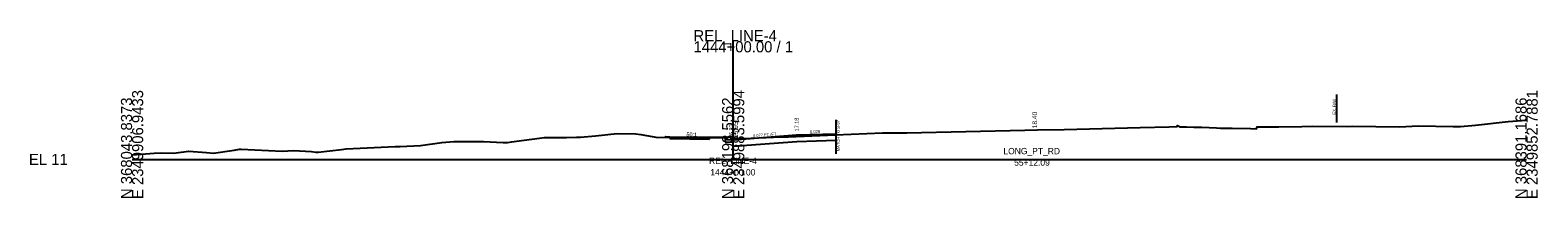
# Model space of a CAD drawing. Extents: x -26 to 2350146, y -10 to 368200.
# Drawn here: x 1974.3 to 2354.4, y 4490.3 to 4532.6 of the extents above; entities that cross this region are included whole.
import ezdxf

# ---------------------------------------------------------------- set-up
doc = ezdxf.new("R2010")
doc.units = 0
for name, color, linetype in [('RD_GPK_XS_Cell', 7, 'Continuous'), ('RD_XS_Base', 7, 'Continuous'), ('RD_XS_CurbBase', 7, 'Continuous'), ('RD_XS_CurbFront', 7, 'Continuous'), ('RD_XS_CurbTop', 7, 'Continuous'), ('RD_XS_EarthShd', 7, 'Continuous'), ('RD_XS_ExGround', 7, 'Continuous'), ('RD_XS_ExRW', 7, 'Continuous'), ('RD_XS_Pave', 7, 'Continuous'), ('RD_XS_SW', 7, 'Continuous'), ('RD_XS_SWbase', 7, 'Continuous'), ('RD_XS_TieSlope', 7, 'Continuous'), ('RD_XS_TX_Elev_EX', 7, 'Continuous'), ('RD_XS_TX_Elev_PR', 7, 'Continuous'), ('RD_XS_TX_MatchLine', 7, 'Continuous'), ('RD_XS_TX_Slope', 7, 'Continuous'), ('RD_XS_TX_Station', 7, 'Continuous'), ('RD_XS_TX_TOC', 7, 'Continuous')]:
    doc.layers.add(name, color=color, linetype=linetype)

msp = doc.modelspace()

# ---------------------------------------------------------------- linework, layer by layer
at = {"layer": 'RD_GPK_XS_Cell'}
for p, q in [((2151.53, 4500), (2151.53, 4529.79)), ((2000, 4500), (2151.53, 4500)), ((2151.53, 4500), (2351.53, 4500))]:
    msp.add_line(p, q, dxfattribs=at)
at = {"layer": 'RD_XS_Base'}
for p, q in [((2151.53, 4503.31), (2167.61, 4504.55)), ((2167.61, 4504.55), (2177.45, 4504.83))]:
    msp.add_line(p, q, dxfattribs=at)
at = {"layer": 'RD_XS_CurbBase'}
for p, q in [((2149.53, 4505.35), (2149.53, 4504.35)), ((2149.53, 4504.35), (2150.03, 4504.35)), ((2150.03, 4504.35), (2151.53, 4504.43)), ((2151.53, 4503.31), (2151.53, 4504.43))]:
    msp.add_line(p, q, dxfattribs=at)
at = {"layer": 'RD_XS_CurbFront'}
msp.add_line((2151.53, 4504.43), (2151.53, 4504.93), dxfattribs=at)
at = {"layer": 'RD_XS_CurbTop'}
for p, q in [((2150.03, 4505.35), (2149.53, 4505.35)), ((2150.11, 4504.85), (2150.03, 4505.35)), ((2151.53, 4504.93), (2150.11, 4504.85)), ((2151.53, 4504.95), (2151.53, 4504.93))]:
    msp.add_line(p, q, dxfattribs=at)
at = {"layer": 'RD_XS_EarthShd'}
for p, q in [((2135.53, 4505.63), (2134.53, 4505.65)), ((2149.53, 4505.35), (2145.53, 4505.43))]:
    msp.add_line(p, q, dxfattribs=at)
at = {"layer": 'RD_XS_ExGround'}
msp.add_lwpolyline([(2000, 4501.13), (2005.54, 4501.58), (2007.53, 4501.62), (2010.44, 4501.58), (2014.34, 4502.08), (2018.8, 4501.72), (2020.51, 4501.59), (2025.7, 4502.37), (2027.08, 4502.55), (2027.5, 4502.56), (2037.82, 4502.04), (2040.66, 4502.24), (2045.21, 4501.96), (2046.31, 4501.84), (2046.9, 4501.83), (2052.77, 4502.5), (2053.96, 4502.65), (2066.36, 4503.28), (2066.98, 4503.27), (2067.62, 4503.28), (2072.71, 4503.48), (2078.06, 4504.27), (2080.1, 4504.4), (2081.1, 4504.51), (2088.61, 4504.53), (2093.58, 4504.29), (2094.32, 4504.28), (2094.65, 4504.27), (2095.66, 4504.44), (2103.93, 4505.5), (2109.49, 4505.5), (2112.01, 4505.62), (2113.01, 4505.6), (2116.8, 4505.93), (2122.26, 4506.57), (2126.97, 4506.42), (2128.23, 4506.25), (2132.5, 4505.5), (2135.98, 4505.64), (2143.57, 4505.59), (2150.21, 4505.69), (2150.76, 4505.69), (2150.93, 4505.19), (2151.53, 4505.22), (2152.54, 4505.28), (2156.03, 4505.39), (2163.59, 4505.67), (2165.43, 4505.73), (2189.2, 4506.66), (2190.27, 4506.66), (2195.33, 4506.71), (2225.08, 4507.36), (2228.21, 4507.42), (2234.96, 4507.58), (2254.16, 4508.05), (2261.43, 4508.22), (2263.41, 4508.27), (2263.54, 4508.51), (2264.17, 4508.25), (2265.82, 4508.21), (2267.69, 4508.16), (2269.64, 4508.09), (2273.4, 4507.93), (2274.33, 4507.88), (2277.3, 4507.84), (2281.92, 4507.76), (2283.45, 4507.68), (2283.62, 4508.18), (2284.13, 4508.18), (2285.77, 4508.19), (2289.11, 4508.19), (2294.86, 4508.32), (2297.55, 4508.4), (2306.37, 4508.31), (2307.53, 4508.34), (2313.53, 4508.26), (2319.57, 4508.18), (2324.24, 4508.48), (2333.03, 4508.32), (2334.87, 4508.31), (2338.64, 4508.66), (2346.89, 4509.59), (2351.53, 4509.93)], dxfattribs=at)
at = {"layer": 'RD_XS_ExRW'}
msp.add_line((2303.69, 4509.34), (2303.69, 4516.34), dxfattribs=at)
at = {"layer": 'RD_XS_Pave'}
for p, q in [((2177.45, 4501.38), (2177.45, 4509.95)), ((2151.53, 4504.95), (2167.53, 4506.18)), ((2167.53, 4506.18), (2177.45, 4506.46))]:
    msp.add_line(p, q, dxfattribs=at)
at = {"layer": 'RD_XS_SW'}
msp.add_line((2145.53, 4505.43), (2135.53, 4505.63), dxfattribs=at)
at = {"layer": 'RD_XS_SWbase'}
for p, q in [((2135.53, 4505.63), (2135.53, 4505.29)), ((2135.53, 4505.29), (2145.53, 4505.09)), ((2145.53, 4505.09), (2145.53, 4505.43))]:
    msp.add_line(p, q, dxfattribs=at)
at = {"layer": 'RD_XS_TieSlope'}
msp.add_line((2134.53, 4505.65), (2134.39, 4505.57), dxfattribs=at)

# ---------------------------------------------------------------- texts
at = {"layer": 'RD_GPK_XS_Cell'}
for s, p in [('REL_LINE-4', (2141.53, 4529.79)), ('1444+00.00 / 1', (2141.53, 4526.99)), ('EL 11', (1974, 4498.6))]:
    msp.add_text(s, height=2.8, dxfattribs=at).set_placement(p)
for s, p in [('N 368043.8373', (2000, 4490)), ('E 2349906.9433', (2002.8, 4490)), ('N 368193.5562', (2151.53, 4490)), ('E 2349883.5994', (2154.33, 4490)), ('N 368391.1686', (2351.53, 4490)), ('E 2349852.7881', (2354.33, 4490))]:
    msp.add_text(s, height=2.8, rotation=90, dxfattribs=at).set_placement(p)
at = {"layer": 'RD_XS_ExRW'}
msp.add_text('EX. R/W ', height=0.75, rotation=90, dxfattribs=at).set_placement((2303.43, 4511.29))
at = {"layer": 'RD_XS_TX_Elev_EX'}
msp.add_text('16.22', height=1, rotation=90, dxfattribs=at).set_placement((2151.5, 4505.39))
at = {"layer": 'RD_XS_TX_Elev_PR'}
for s, height, rotation, p in [(' 18.40', 1.2, 90, (2228.13, 4507.4)), (' 15.95', 1.2, 90, (2152.73, 4504.95)), ('17.18', 1, 90, (2168.03, 4507.07)), ('50:1', 1, 358.8542, (2139.74, 4505.81))]:
    msp.add_text(s, height=height, rotation=rotation, dxfattribs=at).set_placement(p)
at = {"layer": 'RD_XS_TX_MatchLine'}
msp.add_text('MATCH TO S-97', height=0.75, rotation=90, dxfattribs=at).set_placement((2178.41, 4502.03))
at = {"layer": 'RD_XS_TX_Slope'}
for s, rotation, p in [('0.077 FT./FT.', 4.3946, (2156.49, 4505.58)), ('0.029', 1.6382, (2170.89, 4506.59))]:
    msp.add_text(s, height=0.75, rotation=rotation, dxfattribs=at).set_placement(p)
at = {"layer": 'RD_XS_TX_Station'}
for s, p in [('REL_LINE-4', (2145.46, 4498.85)), ('LONG_PT_RD', (2219.65, 4501.3)), ('55+12.09', (2222.36, 4498.4)), ('1444+00.00', (2145.76, 4495.95))]:
    msp.add_text(s, height=1.6, dxfattribs=at).set_placement(p)
at = {"layer": 'RD_XS_TX_TOC'}
msp.add_text('TOCLT', height=0.05, dxfattribs=at).set_placement((2150.08, 4505.3))

doc.saveas('drawing.dxf')
